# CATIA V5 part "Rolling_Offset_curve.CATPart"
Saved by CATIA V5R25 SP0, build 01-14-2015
Part number: Part1
Bounding box of the stored display mesh (mm): x -34.79 to 141.747, y 0 to 36.043, z 0 to 120
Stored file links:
  E:\cadcim\GSD_cat_v5-6r2014\Part_files\Rolling_Offset_curve.CATPart
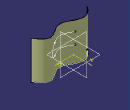
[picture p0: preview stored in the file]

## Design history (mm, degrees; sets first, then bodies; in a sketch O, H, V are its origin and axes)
Set1
  Sketch1 on xy-plane, origin (0, 0, 0), H (1, 0, 0), V (0, 1, 0)
    spline S1 through (141.7471, 7.6193) (96.894, 32.921) (61.2417, 14.2322) (16.9636, 29.4707) (-34.7899, 9.0569)
  Extrude1: Lim1 120, Lim2 0, Element1 Sketch1
  Plane1: type Offset, RefPlane zx-plane, Offset 75
  Sketch2 on Plane1, origin (0, 75, 0), H (-1, 0, 0), V (0, 0, 1)
    line L1 (-21.0945, 87.991) -> (-85.0485, 87.991)
    arc A1 centre (-85.0485, 70.1055) radius 17.8854 from (-85.0485, 87.991) to (-85.0485, 52.2201) ccw
    line L2 (-85.0485, 52.2201) -> (-21.0945, 52.2201)
    horizontal: L1 H
    tangency: A1 L1, L2 A1
  Project1: ToProject Sketch2, Support Extrude1, Direction zx-plane
Body1 (main body)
